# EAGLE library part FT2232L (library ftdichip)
USB UART / FIFO Controller 3nd Generation USB Double-UART (USB <-> Serial) - FIFO Controller
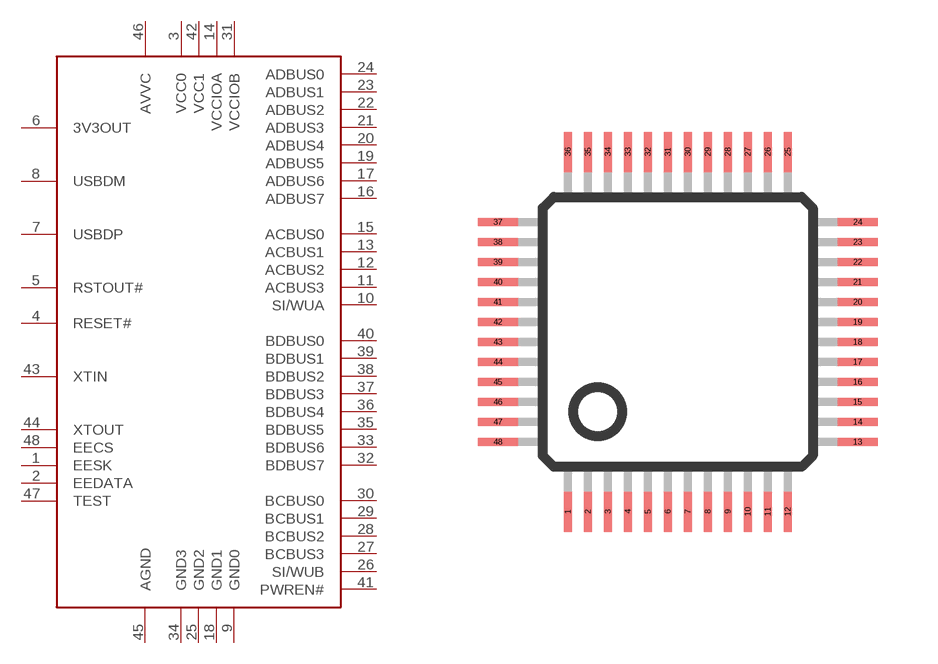
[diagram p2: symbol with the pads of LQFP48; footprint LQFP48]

Designator prefix IC

## FT2232L  [LQFP48]
1  EESK
2  EEDATA
3  VCC0
4  RESET#
5  RSTOUT#
6  3V3OUT
7  USBDP
8  USBDM
9  GND0
10  SI/WUA
11  ACBUS3
12  ACBUS2
13  ACBUS1
14  VCCIOA
15  ACBUS0
16  ADBUS7
17  ADBUS6
18  GND1
19  ADBUS5
20  ADBUS4
21  ADBUS3
22  ADBUS2
23  ADBUS1
24  ADBUS0
25  GND2
26  SI/WUB
27  BCBUS3
28  BCBUS2
29  BCBUS1
30  BCBUS0
31  VCCIOB
32  BDBUS7
33  BDBUS6
34  GND3
35  BDBUS5
36  BDBUS4
37  BDBUS3
38  BDBUS2
39  BDBUS1
40  BDBUS0
41  PWREN#
42  VCC1
43  XTIN
44  XTOUT
45  AGND
46  AVVC
47  TEST
48  EECS

## Footprint LQFP48 (pad centres in mm)
smd 0.2 x 1: 1 -2.75,-4.5; 2 -2.25,-4.5; 3 -1.75,-4.5; 4 -1.25,-4.5; 5 -0.75,-4.5; 6 -0.25,-4.5; 7 0.25,-4.5; 8 0.75,-4.5; 9 1.25,-4.5; 10 1.75,-4.5; 11 2.25,-4.5; 12 2.75,-4.5; 25 2.75,4.5; 26 2.25,4.5; 27 1.75,4.5; 28 1.25,4.5; 29 0.75,4.5; 30 0.25,4.5; 31 -0.25,4.5; 32 -0.75,4.5; 33 -1.25,4.5; 34 -1.75,4.5; 35 -2.25,4.5; 36 -2.75,4.5
smd 1 x 0.2: 13 4.5,-2.75; 14 4.5,-2.25; 15 4.5,-1.75; 16 4.5,-1.25; 17 4.5,-0.75; 18 4.5,-0.25; 19 4.5,0.25; 20 4.5,0.75; 21 4.5,1.25; 22 4.5,1.75; 23 4.5,2.25; 24 4.5,2.75; 37 -4.5,2.75; 38 -4.5,2.25; 39 -4.5,1.75; 40 -4.5,1.25; 41 -4.5,0.75; 42 -4.5,0.25; 43 -4.5,-0.25; 44 -4.5,-0.75; 45 -4.5,-1.25; 46 -4.5,-1.75; 47 -4.5,-2.25; 48 -4.5,-2.75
